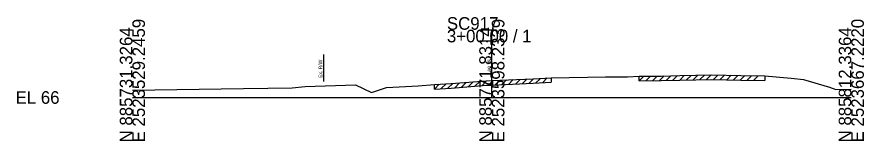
# Model space of a CAD drawing. Extents: x -26 to 218, y -10 to 12021.
# Drawn here: x -25.7 to 162.8, y 2990.3 to 3017.9 of the extents above; entities that cross this region are included whole.
import ezdxf

# ---------------------------------------------------------------- set-up
doc = ezdxf.new("R2010")
doc.units = 0
for name, color, linetype in [('RD_GPK_XS_Cell', 7, 'Continuous'), ('RD_XS_ExGround', 7, 'Continuous'), ('RD_XS_ExPaveRet', 7, 'Continuous'), ('RD_XS_ExRW', 7, 'Continuous'), ('RD_XS_TX_Elev_EX', 7, 'Continuous')]:
    doc.layers.add(name, color=color, linetype=linetype)

msp = doc.modelspace()

# ---------------------------------------------------------------- linework, layer by layer
at = {"layer": 'RD_GPK_XS_Cell'}
for p, q in [((80, 3000), (80, 3015.06)), ((0, 3000), (80, 3000)), ((80, 3000), (160, 3000))]:
    msp.add_line(p, q, dxfattribs=at)
at = {"layer": 'RD_XS_ExGround'}
for p, q in [((70.98, 3003.09), (78.82, 3003.7)), ((78.82, 3003.7), (80, 3003.75)), ((80, 3003.75), (89.18, 3004.16)), ((89.18, 3004.16), (93.24, 3004.39)), ((93.24, 3004.39), (105.29, 3004.59)), ((105.29, 3004.59), (110.2, 3004.61)), ((110.2, 3004.61), (112.81, 3004.72)), ((112.81, 3004.72), (117.72, 3004.77)), ((117.72, 3004.77), (121.87, 3004.86)), ((121.87, 3004.86), (128.99, 3005.02)), ((128.99, 3005.02), (135.41, 3004.88)), ((135.41, 3004.88), (140.75, 3004.78)), ((140.75, 3004.78), (146.62, 3004.26)), ((146.62, 3004.26), (149.39, 3003.98)), ((149.39, 3003.98), (155.16, 3002.28)), ((0, 3001.6), (24.72, 3001.97)), ((24.72, 3001.97), (35.54, 3002.16)), ((35.54, 3002.16), (38.45, 3002.45)), ((38.45, 3002.45), (49.64, 3002.78)), ((49.64, 3002.78), (53.22, 3001.08)), ((53.22, 3001.08), (56.56, 3002.22)), ((56.56, 3002.22), (63.59, 3002.59)), ((63.59, 3002.59), (67.24, 3002.87)), ((67.24, 3002.87), (70.98, 3003.09)), ((155.16, 3002.28), (156.57, 3001.79)), ((156.57, 3001.79), (160, 3001.82))]:
    msp.add_line(p, q, dxfattribs=at)
at = {"layer": 'RD_XS_ExPaveRet'}
for p, q in [((73.24, 3002.26), (74.32, 3003.35)), ((74.74, 3002.38), (75.82, 3003.46)), ((76.24, 3002.5), (77.32, 3003.58)), ((77.74, 3002.61), (78.82, 3003.7)), ((79.24, 3002.71), (80.28, 3003.76)), ((80.74, 3002.78), (81.78, 3003.83)), ((82.24, 3002.85), (83.28, 3003.9)), ((83.74, 3002.92), (84.78, 3003.96)), ((85.24, 3002.98), (86.28, 3004.03)), ((86.74, 3003.05), (87.78, 3004.1)), ((88.24, 3003.12), (89.29, 3004.17)), ((89.18, 3003.16), (93.24, 3003.39)), ((89.74, 3003.19), (90.8, 3004.25)), ((91.24, 3003.28), (92.3, 3004.34)), ((93.24, 3004.39), (93.24, 3003.39)), ((112.81, 3003.72), (113.82, 3004.73)), ((112.81, 3003.72), (112.81, 3004.72)), ((112.81, 3003.72), (117.72, 3003.77)), ((114.31, 3003.74), (115.32, 3004.75)), ((115.81, 3003.75), (116.82, 3004.76)), ((117.31, 3003.77), (118.32, 3004.78)), ((117.72, 3003.77), (121.87, 3003.86)), ((118.81, 3003.8), (119.83, 3004.82)), ((120.31, 3003.83), (121.33, 3004.85)), ((121.81, 3003.86), (122.83, 3004.89)), ((121.87, 3003.86), (128.99, 3004.02)), ((123.31, 3003.9), (124.33, 3004.92)), ((124.81, 3003.93), (125.83, 3004.95)), ((126.31, 3003.96), (127.33, 3004.98)), ((127.81, 3004), (128.83, 3005.02)), ((128.99, 3004.02), (135.41, 3003.88)), ((129.31, 3004.01), (130.28, 3004.99)), ((130.81, 3003.98), (131.78, 3004.96)), ((132.31, 3003.95), (133.28, 3004.93)), ((133.81, 3003.92), (134.78, 3004.9)), ((135.31, 3003.89), (136.29, 3004.87)), ((135.41, 3003.88), (140.75, 3003.78)), ((136.81, 3003.86), (137.79, 3004.84)), ((138.31, 3003.83), (139.29, 3004.81)), ((140.75, 3004.78), (140.75, 3003.78)), ((67.24, 3001.87), (68.3, 3002.93)), ((67.24, 3001.87), (67.24, 3002.87)), ((67.24, 3001.87), (70.98, 3002.09)), ((68.74, 3001.96), (69.8, 3003.02)), ((70.24, 3002.05), (71.31, 3003.12)), ((70.98, 3002.09), (78.82, 3002.7)), ((71.74, 3002.15), (72.82, 3003.23)), ((78.82, 3002.7), (80, 3002.75)), ((80, 3002.75), (89.18, 3003.16))]:
    msp.add_line(p, q, dxfattribs=at)
at = {"layer": 'RD_XS_ExRW'}
msp.add_line((42.5, 3009.57), (42.5, 3003.57), dxfattribs=at)

# ---------------------------------------------------------------- texts
at = {"layer": 'RD_GPK_XS_Cell'}
for s, p in [('E 2523529.2459', (2.8, 2990)), ('E 2523598.2339', (82.8, 2990)), ('E 2523667.2220', (162.8, 2990)), ('N 885731.3264', (0, 2990)), ('N 885771.8314', (80, 2990)), ('N 885812.3364', (160, 2990))]:
    msp.add_text(s, height=2.8, rotation=90, dxfattribs=at).set_placement(p)
for s, p in [('SC917', (70, 3015.06)), ('3+00.00 / 1', (70, 3012.26)), ('EL 66', (-26, 2998.6))]:
    msp.add_text(s, height=2.8, dxfattribs=at).set_placement(p)
at = {"layer": 'RD_XS_ExRW'}
msp.add_text('Ex. R/W ', height=0.8, rotation=90, dxfattribs=at).set_placement((42.25, 3004.36))
at = {"layer": 'RD_XS_TX_Elev_EX'}
msp.add_text('69.75', height=0.8, rotation=90, dxfattribs=at).set_placement((79.9, 3005.75))

doc.saveas('drawing.dxf')
